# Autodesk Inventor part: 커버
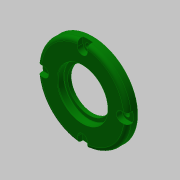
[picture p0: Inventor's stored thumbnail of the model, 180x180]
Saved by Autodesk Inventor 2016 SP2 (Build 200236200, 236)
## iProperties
Created: 2019-05
Part Number: 커버
Material: 알루미늄 6061
Document SubType Name: Modeling
Designer: mduedu
Density: 1 g/cm^3
Appearance: 진녹색
Author: mduedu
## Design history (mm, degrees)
sketch "스케치1"
  geometry: L1 (0, 0)-(36, 0); L2 (36, 0)-(36, -8); L3 (36, -8)-(0, -8); L4 (0, -8)-(0, 0); L5 (0, -8)-(26, -8); L6 (26, -8)-(26, -12); L7 (26, -12)-(0, -12); L8 (0, -12)-(0, -8)
  constraints: 16 end point, 4 parallel, 2 horizontal, 2 perpendicular
  dimensions: "d0" = 72 diameter of L2 L4; "d2" = 52 diameter of L6 L8; "d3" = 12 distance between parallel lines of L7 L1; "d4" = 4 distance between parallel lines of L7 L3
revolve "회전1" sketch "스케치1" stored, may be unused: angle "d5" = 90 deg
sketch "스케치2" dims "d6" = 62
  geometry: L1 (-4, 31)-(-4, 35.777); L2 (4, 31)-(4, 35.777); A1 r 4 centre (0, 31) between (-4, 31) and (4, 31); A2 r 36 centre (0, 0) between (-4, 35.777) and (4, 35.777) reference; A3 r 36 centre (0, 0) between (4, 35.777) and (-4, 35.777); 2 further points
  constraints: 6 point on circle, 4 end point, 2 centre point, 2 coincident, 2 tangent, 2 vertical alignment, 1 parallel, 1 vertical, 2 other
  dimensions: "d7" = 8 distance between parallel lines of L2 L1
extrude "돌출1" cut sketch "스케치2" distance "d8" = 4.4; taper "d9" = 0 deg
fillet "모깎기1" dims "d13" = 3
sketch "스케치3"
  geometry: L1 (36, -4.4)-(36, -8) reference; L2 (36, -8)-(26, -8) reference; L3 (26, -8)-(26, -12) reference; L4 (26, -12)-(-26, -12) reference; L5 (-26, -12)-(-26, -8) reference; L6 (-26, -8)-(-36, -8) reference; L7 (-36, -8)-(-36, -4.4) reference; L8 (-36, -4.4)-(-27, -4.4) reference; L9 (-27, -4.4)-(-27, 0) reference; L10 (-27, 0)-(27, 0) reference; L11 (27, 0)-(27, -4.4) reference; L12 (27, -4.4)-(36, -4.4) reference; L13 (0, 0)-(20, 0); L14 (20, 0)-(20, -5.2); L15 (20, -5.2)-(0, -5.2); L16 (0, -5.2)-(0, 0); L17 (0, -5.2)-(17, -5.2); L18 (17, -5.2)-(17, -8); L19 (17, -8)-(0, -8); L20 (0, -8)-(0, -5.2); L21 (0, -8)-(23, -8); L22 (23, -8)-(23, -12); L23 (23, -12)-(0, -12); L24 (0, -12)-(0, -8)
  constraints: 24 end point, 6 parallel, 3 horizontal, 3 perpendicular, 1 point on line
  dimensions: "d14" = 40 diameter of L14 L16; "d16" = 5.2 distance of L13.end L14.end; "d17" = 46 diameter of L22 L24; "d18" = 4 distance of L21.end L22.end; "d19" = 34 diameter of L18 L20
revolve "회전2" sketch "스케치3" stored, may be unused: angle "d20" = 90 deg
chamfer "모따기1" distance "d21" = 0.5; stored, may be unused: second distance "d22" = 2, angle "d23" = 30 deg
fillet "모깎기2" dims "d24" = 0.2
fillet "모깎기3" dims "d25" = 3
chamfer "모따기2" distance "d26" = 1; stored, may be unused: second distance "d27" = 2, angle "d28" = 30 deg
sketch "스케치4" dims "d29" = 62
  geometry: 6 further points
  constraints: 2 vertical alignment, 1 coincident, 7 other
  dimensions: "d32" = 360 deg dimension on point (0, 0) point (0, 31) (derived)
sketch "스케치5"
  geometry: 4 further points
  constraints: 4 other
hole "구멍1" sketch "스케치5" at (-31, 0), (0, -31), (31, 0), (0, 31) diameter "d34" = 4.5; stored, may be unused: countersink angle "d38" = 90 deg, drill point angle "d40" = 0 deg; dims "d35" = 6, "d36" = 4, "d37" = 2, "d39" = 8
node "솔리드1"
pattern_circular "원형 패턴1" dims angle "d11" = 360 deg
node "절단 모서리 투영1"
